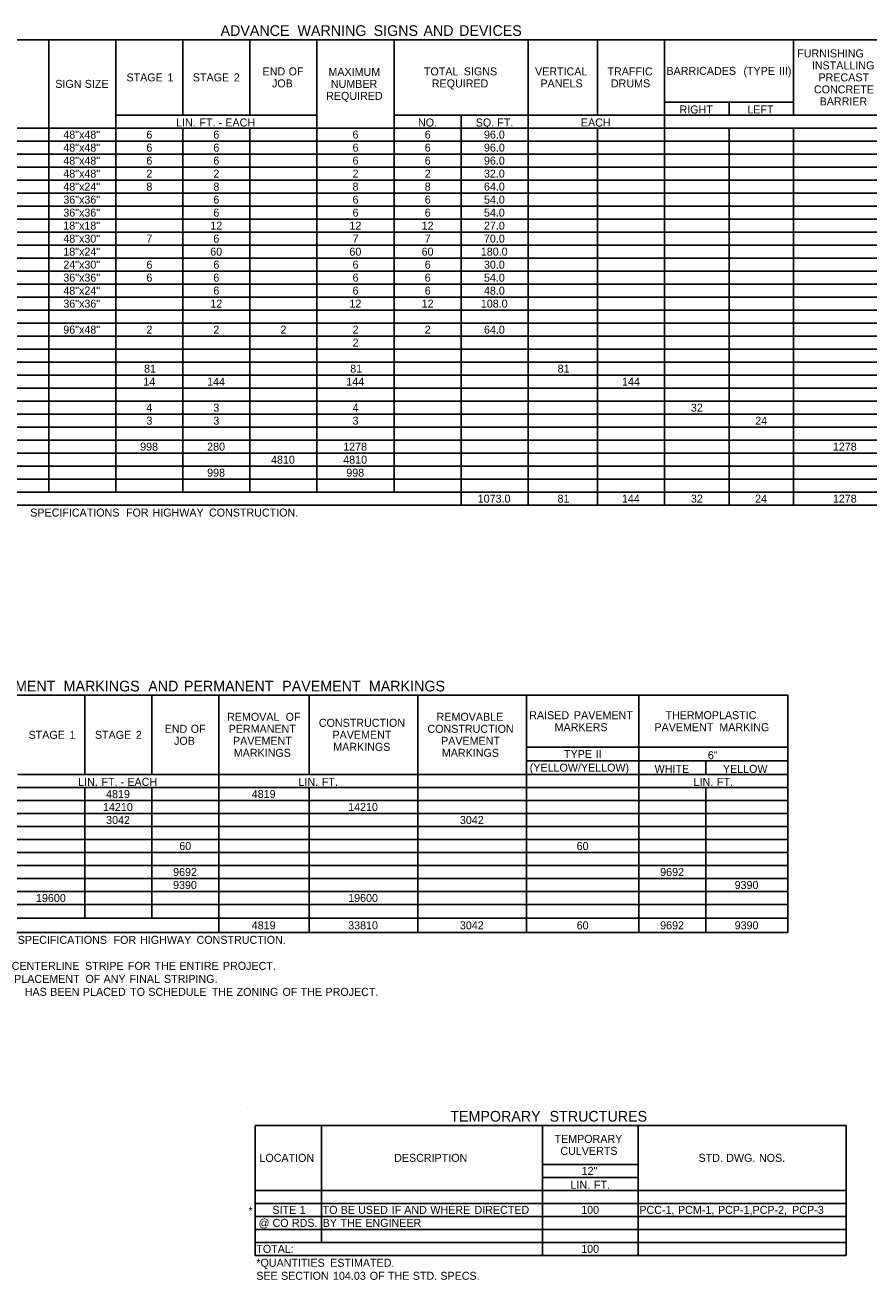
# Model space of a CAD drawing. Extents: x 977434 to 989596, y 1525697 to 1528336.
# Drawn here: x 979473 to 980105, y 1527367 to 1528308 of the extents above; entities that cross this region are included whole.
import ezdxf

# ---------------------------------------------------------------- set-up
doc = ezdxf.new("R2010")
doc.units = 0
doc.layers.add('Default', color=7, linetype='Continuous')
doc.layers.add('R_Border Prem', color=7, linetype='Continuous')

msp = doc.modelspace()

# ---------------------------------------------------------------- linework, layer by layer
at = {"layer": 'Default'}
for p, q in [((979105.72, 1528296.72), (980364.94, 1528296.72)), ((979490.36, 1527957.42), (979490.36, 1528296.72)), ((979540.57, 1527957.42), (979540.57, 1528296.72)), ((979590.79, 1528240.17), (979590.79, 1528296.72)), ((979641, 1528240.17), (979641, 1528296.72)), ((979691.21, 1527957.42), (979691.21, 1528296.72)), ((979749.22, 1527957.42), (979749.22, 1528296.72)), ((979849.65, 1527947.67), (979849.65, 1528296.72)), ((979901.81, 1528240.17), (979901.81, 1528296.72)), ((979952.02, 1527947.67), (979952.02, 1528296.72)), ((980048.55, 1528240.17), (980048.55, 1528296.72)), ((979952.02, 1528249.92), (980048.55, 1528249.92)), ((980000.29, 1528240.17), (980000.29, 1528249.92)), ((980000.29, 1528240.17), (980000.29, 1528249.92)), ((979540.57, 1528240.17), (979691.21, 1528240.17)), ((979749.22, 1528240.17), (980364.94, 1528240.17)), ((979799.44, 1527947.67), (979799.44, 1528240.17)), ((979952.02, 1528240.17), (980000.29, 1528240.17)), ((979952.02, 1527947.67), (979952.02, 1528240.17)), ((980000.29, 1528240.17), (980364.94, 1528240.17)), ((979105.72, 1528230.42), (980364.94, 1528230.42)), ((979490.36, 1527957.42), (979490.36, 1528230.42)), ((979540.57, 1527957.42), (979540.57, 1528230.42)), ((979590.79, 1527957.42), (979590.79, 1528230.42)), ((979590.79, 1527957.42), (979590.79, 1528230.42)), ((979641, 1527957.42), (979641, 1528230.42)), ((979641, 1527957.42), (979641, 1528230.42)), ((979691.21, 1528230.42), (980364.94, 1528230.42)), ((979691.21, 1528103.67), (979691.21, 1528230.42)), ((979799.44, 1527947.67), (979799.44, 1528230.42)), ((979849.65, 1527947.67), (979849.65, 1528230.42)), ((979901.81, 1527947.67), (979901.81, 1528230.42)), ((979901.81, 1527947.67), (979901.81, 1528230.42)), ((980000.29, 1527947.67), (980000.29, 1528230.42)), ((980000.29, 1527947.67), (980000.29, 1528230.42)), ((980048.55, 1527947.67), (980048.55, 1528230.42)), ((980048.55, 1527947.67), (980048.55, 1528230.42)), ((979105.72, 1528220.67), (980364.94, 1528220.67)), ((979105.72, 1528210.92), (980364.94, 1528210.92)), ((979105.72, 1528201.17), (980364.94, 1528201.17)), ((979105.72, 1528191.42), (980364.94, 1528191.42)), ((979105.72, 1528181.67), (980364.94, 1528181.67)), ((979105.72, 1528171.92), (980364.94, 1528171.92)), ((979105.72, 1528162.17), (980364.94, 1528162.17)), ((979105.72, 1528152.42), (980364.94, 1528152.42)), ((979105.72, 1528142.67), (980364.94, 1528142.67)), ((979105.72, 1528132.92), (980364.94, 1528132.92)), ((979105.72, 1528123.17), (980364.94, 1528123.17)), ((979105.72, 1528113.42), (980364.94, 1528113.42)), ((979105.72, 1528103.67), (980364.94, 1528103.67)), ((979105.72, 1528093.92), (980364.94, 1528093.92)), ((979691.21, 1527957.42), (979691.21, 1528093.92)), ((979105.72, 1528084.17), (980364.94, 1528084.17)), ((979105.72, 1528074.42), (980364.94, 1528074.42)), ((979105.72, 1528064.67), (980364.94, 1528064.67)), ((979105.72, 1528054.92), (980364.94, 1528054.92)), ((979105.72, 1528045.17), (980364.94, 1528045.17)), ((979105.72, 1528035.42), (980364.94, 1528035.42)), ((979105.72, 1528025.67), (980364.94, 1528025.67)), ((979105.72, 1528015.92), (980364.94, 1528015.92)), ((979105.72, 1528006.17), (980364.94, 1528006.17)), ((979105.72, 1527996.42), (980364.94, 1527996.42)), ((979105.72, 1527986.67), (980364.94, 1527986.67)), ((979490.36, 1527986.67), (979691.21, 1527986.67)), ((979691.21, 1527986.67), (979749.22, 1527986.67)), ((979749.22, 1527986.67), (980048.55, 1527986.67)), ((980048.55, 1527986.67), (980292.3, 1527986.67)), ((979105.72, 1527976.92), (980364.94, 1527976.92)), ((979490.36, 1527976.92), (979691.21, 1527976.92)), ((979691.21, 1527976.92), (979749.22, 1527976.92)), ((979749.22, 1527976.92), (980048.55, 1527976.92)), ((980048.55, 1527976.92), (980292.3, 1527976.92)), ((979105.72, 1527967.17), (980364.94, 1527967.17)), ((979105.72, 1527957.42), (980364.94, 1527957.42)), ((979105.72, 1527947.67), (980364.94, 1527947.67)), ((979090.8, 1527805.18), (980044.35, 1527805.18)), ((979517.37, 1527745.71), (979517.37, 1527805.18)), ((979567.58, 1527745.71), (979567.58, 1527805.18)), ((979617.79, 1527627.25), (979617.79, 1527805.18)), ((979685.55, 1527745.71), (979685.55, 1527805.18)), ((979766.97, 1527627.25), (979766.97, 1527805.18)), ((979848.38, 1527627.25), (979848.38, 1527805.18)), ((979848.38, 1527766.18), (979848.38, 1527805.18)), ((979932.72, 1527627.25), (979932.72, 1527805.18)), ((980044.35, 1527627.25), (980044.35, 1527805.18)), ((980044.35, 1527627.25), (980044.35, 1527805.18)), ((979848.38, 1527766.18), (980044.35, 1527766.18)), ((979848.38, 1527755.95), (980044.35, 1527755.95)), ((979982.93, 1527745.71), (979982.93, 1527755.95)), ((979467.15, 1527745.71), (980044.35, 1527745.71)), ((979766.97, 1527627.25), (979766.97, 1527745.71)), ((979848.38, 1527627.25), (979848.38, 1527745.71)), ((979932.72, 1527627.25), (979932.72, 1527745.71)), ((979090.8, 1527735.96), (980044.35, 1527735.96)), ((979517.37, 1527637.97), (979517.37, 1527735.96)), ((979517.37, 1527637.97), (979517.37, 1527735.96)), ((979567.58, 1527637.97), (979567.58, 1527735.96)), ((979567.58, 1527637.97), (979567.58, 1527735.96)), ((979617.79, 1527627.25), (979617.79, 1527735.96)), ((979685.55, 1527627.25), (979685.55, 1527735.96)), ((979685.55, 1527627.25), (979685.55, 1527735.96)), ((979982.93, 1527627.25), (979982.93, 1527735.96)), ((979982.93, 1527627.25), (979982.93, 1527735.96)), ((979090.8, 1527726.21), (980044.35, 1527726.21)), ((979090.8, 1527716.46), (980044.35, 1527716.46)), ((979090.8, 1527706.71), (980044.35, 1527706.71)), ((979090.8, 1527696.96), (980044.35, 1527696.96)), ((979090.8, 1527687.21), (980044.35, 1527687.21)), ((979090.8, 1527677.46), (980044.35, 1527677.46)), ((979090.8, 1527667.71), (980044.35, 1527667.71)), ((979090.8, 1527657.96), (980044.35, 1527657.96)), ((979090.8, 1527648.21), (980044.35, 1527648.21)), ((979090.8, 1527637.97), (980044.35, 1527637.97)), ((979090.8, 1527627.25), (980044.35, 1527627.25)), ((979644.98, 1527482.59), (980088.12, 1527482.59)), ((979644.98, 1527385.09), (979644.98, 1527482.59)), ((979644.98, 1527385.09), (979644.98, 1527482.59)), ((979694.71, 1527394.84), (979694.71, 1527482.59)), ((979860.46, 1527385.09), (979860.46, 1527482.59)), ((979932.12, 1527385.09), (979932.12, 1527482.59)), ((979932.12, 1527385.09), (979932.12, 1527482.59)), ((980088.12, 1527385.09), (980088.12, 1527482.59)), ((979860.46, 1527453.34), (979932.12, 1527453.34)), ((979860.46, 1527443.59), (979932.12, 1527443.59)), ((979644.98, 1527433.84), (980088.12, 1527433.84)), ((979694.71, 1527394.84), (979694.71, 1527433.84)), ((979932.12, 1527433.84), (980088.12, 1527433.84)), ((979644.98, 1527424.09), (980088.12, 1527424.09)), ((979644.98, 1527414.34), (980088.12, 1527414.34)), ((980088.12, 1527385.09), (980088.12, 1527414.34)), ((979644.98, 1527404.59), (980088.12, 1527404.59)), ((979644.98, 1527394.84), (980088.12, 1527394.84)), ((979694.71, 1527394.84), (979860.46, 1527394.84)), ((979860.46, 1527394.84), (980088.12, 1527394.84)), ((979644.98, 1527385.09), (980088.12, 1527385.09))]:
    msp.add_line(p, q, dxfattribs=at)
at = {"layer": 'R_Border Prem'}
msp.add_line((979639.13, 1527496.24), (979639.13, 1527496.24), dxfattribs=at)

# ---------------------------------------------------------------- texts
at = {"layer": 'Default'}
for s, height, p in [('ADVANCE', 8, (979619.12, 1528299.54)), (' WARNING', 8, (979673.85, 1528299.54)), (' SIGNS', 8, (979730.92, 1528299.54)), (' AND', 8, (979768.26, 1528299.54)), (' DEVICES', 8, (979795.03, 1528299.54)), ('FURNISHING', 6, (980051.44, 1528283.44)), ('END', 6, (979650.67, 1528269.94)), (' OF', 6, (979667.96, 1528269.94)), ('MAXIMUM', 6, (979700.03, 1528269.57)), ('TOTAL', 6, (979771.59, 1528269.94)), (' SIGNS', 6, (979799.28, 1528269.94)), ('VERTICAL', 6, (979854.89, 1528269.94)), ('TRAFFIC', 6, (979909.2, 1528269.94)), ('BARRICADES', 6, (979953.41, 1528270.32)), (' (TYPE', 6, (980008.89, 1528270.32)), (' III)', 6, (980035.5, 1528270.32)), ('INSTALLING', 6, (980062.41, 1528274.44)), ('SIGN', 6, (979495.28, 1528260.57)), (' SIZE', 6, (979515.11, 1528260.57)), ('STAGE', 6, (979548.63, 1528265.44)), (' 1', 6, (979577.1, 1528265.44)), ('STAGE', 6, (979598.37, 1528265.44)), (' 2', 6, (979626.84, 1528265.44)), ('JOB', 6, (979657.69, 1528260.94)), ('NUMBER', 6, (979701.84, 1528260.57)), ('REQUIRED', 6, (979777.52, 1528260.94)), ('PANELS', 6, (979858.93, 1528260.94)), ('DRUMS', 6, (979911.75, 1528260.94)), ('PRECAST', 6, (980067.36, 1528265.44)), ('REQUIRED', 6, (979698.3, 1528251.57)), ('CONCRETE', 6, (980063.99, 1528256.44)), ('RIGHT', 6, (979963.2, 1528241.37)), ('LEFT', 6, (980014.02, 1528241.37)), ('BARRIER', 6, (980068.23, 1528247.44)), ('LIN.', 6, (979585.85, 1528231.62)), (' FT.', 6, (979601.11, 1528231.62)), (' EACH', 6, (979620.49, 1528231.62)), ('NO.', 6, (979767.17, 1528231.62)), ('SQ.', 6, (979810.45, 1528231.62)), (' FT.', 6, (979824.31, 1528231.62)), ('EACH', 6, (979889.28, 1528231.62)), ('48"x48"', 6, (979501.27, 1528222.54)), ('6', 6, (979563.54, 1528222.54)), ('6', 6, (979613.75, 1528222.54)), (' -', 6, (979615.43, 1528231.62)), ('6', 6, (979718.08, 1528222.54)), ('6', 6, (979772.19, 1528222.54)), ('96.0', 6, (979816.59, 1528222.54)), ('48"x48"', 6, (979501.27, 1528212.79)), ('6', 6, (979563.54, 1528212.79)), ('6', 6, (979613.75, 1528212.79)), ('6', 6, (979718.08, 1528212.79)), ('6', 6, (979772.19, 1528212.79)), ('96.0', 6, (979816.59, 1528212.79)), ('48"x48"', 6, (979501.27, 1528203.04)), ('6', 6, (979563.54, 1528203.04)), ('6', 6, (979613.75, 1528203.04)), ('6', 6, (979718.08, 1528203.04)), ('6', 6, (979772.19, 1528203.04)), ('96.0', 6, (979816.59, 1528203.04)), ('48"x48"', 6, (979501.27, 1528193.29)), ('2', 6, (979563.57, 1528193.29)), ('2', 6, (979613.78, 1528193.29)), ('2', 6, (979718.11, 1528193.29)), ('2', 6, (979772.22, 1528193.29)), ('32.0', 6, (979816.59, 1528193.29)), ('48"x24"', 6, (979501.27, 1528183.54)), ('8', 6, (979563.53, 1528183.54)), ('8', 6, (979613.75, 1528183.54)), ('8', 6, (979718.07, 1528183.54)), ('8', 6, (979772.18, 1528183.54)), ('64.0', 6, (979816.59, 1528183.54)), ('36"x36"', 6, (979501.27, 1528173.79)), ('6', 6, (979613.75, 1528173.79)), ('6', 6, (979718.08, 1528173.79)), ('6', 6, (979772.19, 1528173.79)), ('54.0', 6, (979816.59, 1528173.79)), ('36"x36"', 6, (979501.27, 1528164.04)), ('6', 6, (979613.75, 1528164.04)), ('6', 6, (979718.08, 1528164.04)), ('6', 6, (979772.19, 1528164.04)), ('54.0', 6, (979816.59, 1528164.04)), ('18"x18"', 6, (979501.27, 1528154.29)), ('12', 6, (979611.45, 1528154.29)), ('12', 6, (979715.78, 1528154.29)), ('12', 6, (979769.89, 1528154.29)), ('27.0', 6, (979816.59, 1528154.29)), ('48"x30"', 6, (979501.27, 1528144.54)), ('7', 6, (979563.54, 1528144.54)), ('6', 6, (979613.75, 1528144.54)), ('7', 6, (979718.08, 1528144.54)), ('7', 6, (979772.19, 1528144.54)), ('70.0', 6, (979816.59, 1528144.54)), ('18"x24"', 6, (979501.27, 1528134.79)), ('60', 6, (979611.43, 1528134.79)), ('60', 6, (979715.76, 1528134.79)), ('60', 6, (979769.87, 1528134.79)), ('180.0', 6, (979814.26, 1528134.79)), ('24"x30"', 6, (979501.27, 1528125.04)), ('6', 6, (979563.54, 1528125.04)), ('6', 6, (979613.75, 1528125.04)), ('6', 6, (979718.08, 1528125.04)), ('6', 6, (979772.19, 1528125.04)), ('30.0', 6, (979816.59, 1528125.04)), ('36"x36"', 6, (979501.27, 1528115.29)), ('6', 6, (979563.54, 1528115.29)), ('6', 6, (979613.75, 1528115.29)), ('6', 6, (979718.08, 1528115.29)), ('6', 6, (979772.19, 1528115.29)), ('54.0', 6, (979816.59, 1528115.29)), ('48"x24"', 6, (979501.27, 1528105.54)), ('6', 6, (979613.75, 1528105.54)), ('6', 6, (979718.08, 1528105.54)), ('6', 6, (979772.19, 1528105.54)), ('48.0', 6, (979816.59, 1528105.54)), ('36"x36"', 6, (979501.27, 1528095.79)), ('12', 6, (979611.45, 1528095.79)), ('12', 6, (979715.78, 1528095.79)), ('12', 6, (979769.89, 1528095.79)), ('108.0', 6, (979814.26, 1528095.79)), ('96"x48"', 6, (979501.27, 1528076.29)), ('2', 6, (979563.57, 1528076.29)), ('2', 6, (979613.78, 1528076.29)), ('2', 6, (979664, 1528076.29)), ('2', 6, (979718.11, 1528076.29)), ('2', 6, (979772.22, 1528076.29)), ('64.0', 6, (979816.59, 1528076.29)), ('2', 6, (979718.11, 1528066.54)), ('81', 6, (979561.79, 1528047.04)), ('81', 6, (979716.33, 1528047.04)), ('81', 6, (979871.84, 1528047.04)), ('14', 6, (979561.22, 1528037.29)), ('144', 6, (979609.1, 1528037.29)), ('144', 6, (979713.43, 1528037.29)), ('144', 6, (979920.13, 1528037.29)), ('4', 6, (979563.55, 1528017.79)), ('3', 6, (979613.75, 1528017.79)), ('4', 6, (979718.09, 1528017.79)), ('32', 6, (979971.72, 1528017.79)), ('3', 6, (979563.54, 1528008.04)), ('3', 6, (979613.75, 1528008.04)), ('3', 6, (979718.08, 1528008.04)), ('24', 6, (980019.96, 1528008.04)), ('998', 6, (979558.87, 1527988.54)), ('280', 6, (979609.1, 1527988.54)), ('1278', 6, (979711.08, 1527988.54)), ('1278', 6, (980078.17, 1527988.54)), ('4810', 6, (979656.99, 1527978.79)), ('4810', 6, (979711.1, 1527978.79)), ('998', 6, (979609.09, 1527969.04)), ('998', 6, (979713.41, 1527969.04)), ('1073.0', 6, (979811.93, 1527949.54)), ('81', 6, (979871.75, 1527949.54)), ('144', 6, (979920.02, 1527949.54)), ('32', 6, (979971.7, 1527949.54)), ('24', 6, (980019.85, 1527949.54)), ('1278', 6, (980078.17, 1527949.54)), (' SPECIFICATIONS', 6, (979474.26, 1527939.12)), (' FOR', 6, (979546.02, 1527939.12)), (' HIGHWAY', 6, (979565.94, 1527939.12)), (' CONSTRUCTION.', 6, (979608.26, 1527939.12)), (' PAVEMENT', 8, (979433.53, 1527808.01)), (' MARKINGS', 8, (979498.52, 1527808.01)), (' AND', 8, (979561.93, 1527808.01)), (' PERMANENT', 8, (979588.7, 1527808.01)), (' PAVEMENT', 8, (979662.38, 1527808.01)), (' MARKINGS', 8, (979727.37, 1527808.01)), ('RAISED', 6, (979850.55, 1527787.18)), (' PAVEMENT', 6, (979881.81, 1527787.18)), ('THERMOPLASTIC', 6, (979952.65, 1527787.18)), (' OF', 6, (979594.54, 1527776.95)), ('REMOVAL', 6, (979624.05, 1527785.95)), (' OF', 6, (979665.72, 1527785.95)), ('CONSTRUCTION', 6, (979692.83, 1527781.45)), ('CONSTRUCTION', 6, (979774.24, 1527776.95)), ('REMOVABLE', 6, (979781.1, 1527785.95)), ('MARKERS', 6, (979869.56, 1527778.18)), ('PAVEMENT', 6, (979944.39, 1527778.18)), (' MARKING', 6, (979990.81, 1527778.18)), ('STAGE', 6, (979475.21, 1527772.45)), (' 1', 6, (979503.68, 1527772.45)), ('STAGE', 6, (979524.96, 1527772.45)), (' 2', 6, (979553.42, 1527772.45)), ('END', 6, (979577.25, 1527776.95)), ('JOB', 6, (979584.27, 1527767.95)), ('PERMANENT', 6, (979625.21, 1527776.95)), ('PAVEMENT', 6, (979628.47, 1527767.95)), ('PAVEMENT', 6, (979703.05, 1527772.45)), ('PAVEMENT', 6, (979784.47, 1527767.95)), ('MARKINGS', 6, (979629.06, 1527758.95)), ('MARKINGS', 6, (979703.64, 1527763.45)), ('MARKINGS', 6, (979785.06, 1527758.95)), ('TYPE', 6, (979876.59, 1527758.06)), (' II', 6, (979898.07, 1527758.06)), ('6"', 6, (979984.43, 1527757.15)), ('(YELLOW/YELLOW)', 6, (979850.95, 1527747.83)), ('WHITE', 6, (979944.53, 1527746.91)), ('YELLOW', 6, (979995.72, 1527746.91)), ('LIN.', 6, (979512.43, 1527737.16)), (' FT.', 6, (979527.69, 1527737.16)), (' -', 6, (979542.01, 1527737.16)), (' EACH', 6, (979547.07, 1527737.16)), ('LIN.', 6, (979677.59, 1527737.16)), (' FT.', 6, (979692.85, 1527737.16)), ('LIN.', 6, (979973.75, 1527737.16)), (' FT.', 6, (979989, 1527737.16)), ('4819', 6, (979533.34, 1527728.08)), ('4819', 6, (979642.54, 1527728.08)), ('14210', 6, (979531.02, 1527718.33)), ('14210', 6, (979714.81, 1527718.33)), ('3042', 6, (979533.37, 1527708.58)), ('3042', 6, (979798.57, 1527708.58)), ('60', 6, (979588.23, 1527689.08)), ('60', 6, (979886.09, 1527689.08)), ('9692', 6, (979583.59, 1527669.58)), ('9692', 6, (979948.72, 1527669.58)), ('9390', 6, (979583.57, 1527659.83)), ('9390', 6, (980004.52, 1527659.83)), ('19600', 6, (979480.81, 1527650.08)), ('19600', 6, (979714.81, 1527650.08)), ('4819', 6, (979642.55, 1527629.61)), ('33810', 6, (979714.82, 1527629.61)), ('3042', 6, (979798.56, 1527629.61)), ('60', 6, (979886.09, 1527629.61)), ('9692', 6, (979948.71, 1527629.61)), ('9390', 6, (980004.53, 1527629.61)), (' SPECIFICATIONS', 6, (979464.93, 1527618.7)), (' FOR', 6, (979536.7, 1527618.7)), (' HIGHWAY', 6, (979556.61, 1527618.7)), (' CONSTRUCTION.', 6, (979598.93, 1527618.7)), (' CENTERLINE', 6, (979460.34, 1527599.2)), (' STRIPE', 6, (979515.33, 1527599.2)), (' FOR', 6, (979547.5, 1527599.2)), (' THE', 6, (979567.41, 1527599.2)), (' ENTIRE', 6, (979586.06, 1527599.2)), (' PROJECT.', 6, (979618.68, 1527599.2)), (' PLACEMENT', 6, (979462.23, 1527589.45)), (' OF', 6, (979515.63, 1527589.45)), (' ANY', 6, (979529.22, 1527589.45)), (' FINAL', 6, (979548.72, 1527589.45)), (' STRIPING.', 6, (979574.51, 1527589.45)), (' HAS', 6, (979470.14, 1527579.7)), (' BEEN', 6, (979489.27, 1527579.7)), (' PLACED', 6, (979513.74, 1527579.7)), (' TO', 6, (979549.17, 1527579.7)), (' SCHEDULE', 6, (979562.77, 1527579.7)), (' THE', 6, (979610.31, 1527579.7)), (' ZONING', 6, (979628.96, 1527579.7)), (' OF', 6, (979663.36, 1527579.7)), (' THE', 6, (979676.95, 1527579.7)), (' PROJECT.', 6, (979695.6, 1527579.7)), ('TEMPORARY', 8, (979791.35, 1527485.42)), (' STRUCTURES', 8, (979862.8, 1527485.42)), ('TEMPORARY', 6, (979869.5, 1527469.47)), ('CULVERTS', 6, (979873.9, 1527460.47)), ('LOCATION', 6, (979648.29, 1527455.22)), ('DESCRIPTION', 6, (979749.27, 1527455.22)), ('STD.', 6, (979977.45, 1527455.22)), (' DWG.', 6, (979995.97, 1527455.22)), (' NOS.', 6, (980020.54, 1527455.22)), ('12"', 6, (979889.85, 1527445.47)), ('LIN.', 6, (979881.5, 1527435.04)), (' FT.', 6, (979896.76, 1527435.04)), ('*', 6, (979640.11, 1527415.54)), ('SITE', 6, (979658.03, 1527416.22)), (' 1', 6, (979676.22, 1527416.22)), ('TO', 6, (979695.68, 1527416.22)), (' BE', 6, (979706.95, 1527416.22)), (' USED', 6, (979720.02, 1527416.22)), (' IF', 6, (979745.19, 1527416.22)), (' AND', 6, (979754.59, 1527416.22)), (' WHERE', 6, (979774.17, 1527416.22)), (' DIRECTED', 6, (979807.26, 1527416.22)), ('100', 6, (979889.5, 1527416.22)), ('PCC-1,', 6, (979933.1, 1527416.22)), (' PCM-1,', 6, (979959.83, 1527416.22)), (' PCP-1,PCP-2,', 6, (979989.82, 1527416.22)), (' PCP-3', 6, (980045.44, 1527416.22)), ('@', 6, (979647.66, 1527406.47)), (' CO', 6, (979655.87, 1527406.47)), (' RDS.', 6, (979670.4, 1527406.47)), ('BY', 6, (979695.68, 1527406.47)), (' THE', 6, (979706.81, 1527406.47)), (' ENGINEER', 6, (979725.46, 1527406.47)), ('TOTAL:', 6, (979645.96, 1527386.97)), ('100', 6, (979889.51, 1527386.97)), ('*QUANTITIES', 6, (979645.96, 1527376.54)), (' ESTIMATED.', 6, (979699.09, 1527376.54)), ('SEE', 6, (979645.96, 1527366.79)), (' SECTION', 6, (979662.29, 1527366.79)), (' 104.03', 6, (979701.2, 1527366.79)), (' OF', 6, (979728.77, 1527366.79)), (' THE', 6, (979742.36, 1527366.79)), (' STD.', 6, (979761.01, 1527366.79)), (' SPECS.', 6, (979781.7, 1527366.79))]:
    msp.add_text(s, height=height, dxfattribs=at).set_placement(p)

doc.saveas('drawing.dxf')
